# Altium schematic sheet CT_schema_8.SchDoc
size 277 x 170 mm
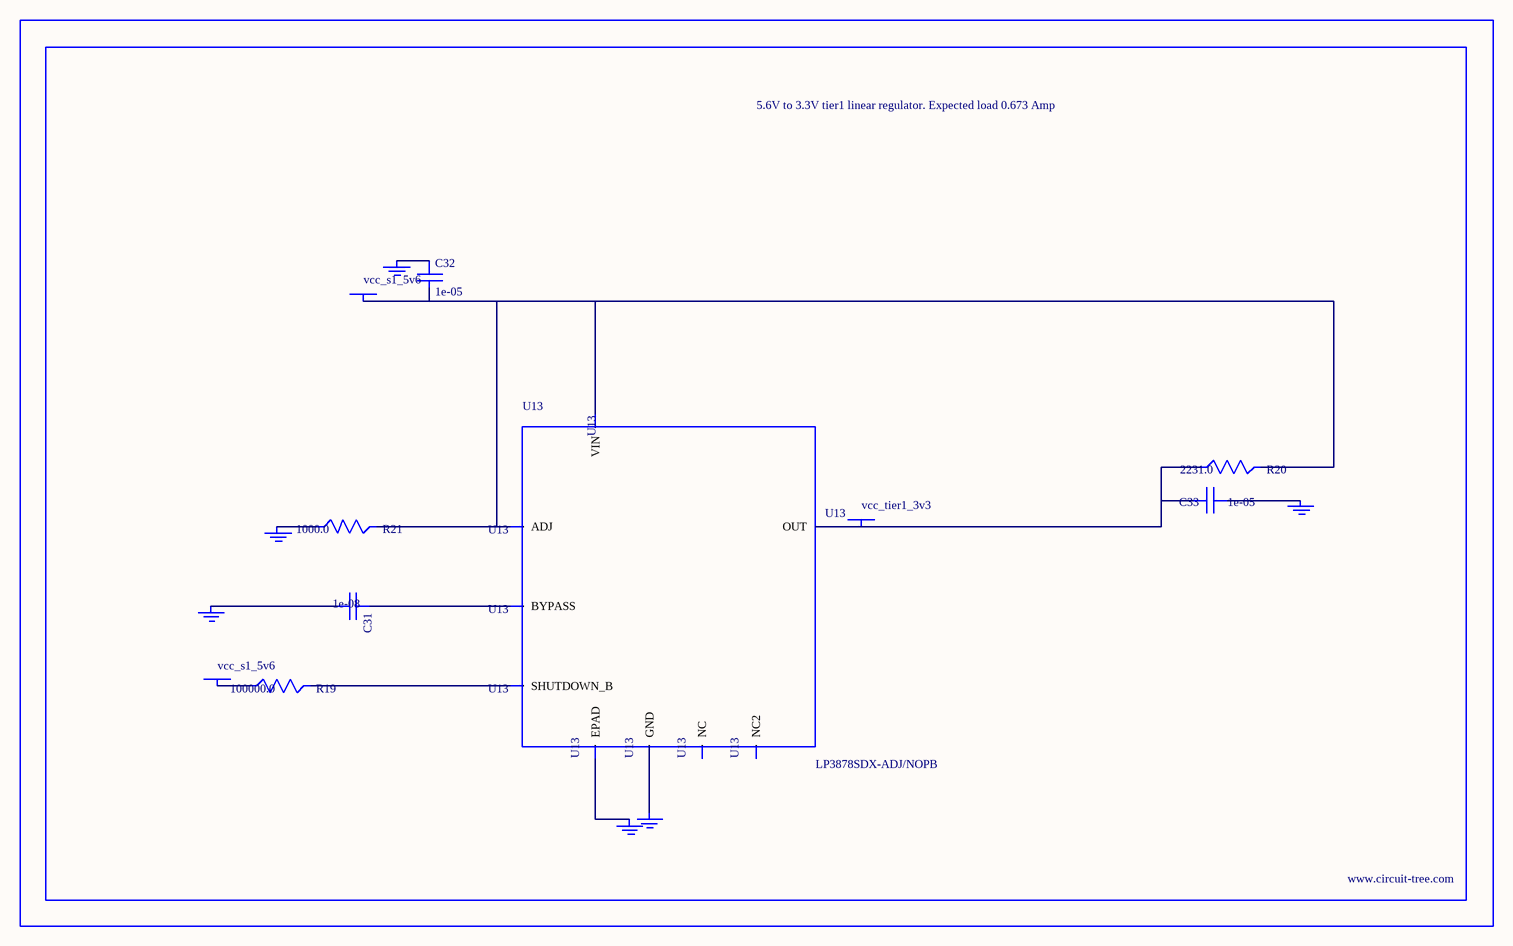
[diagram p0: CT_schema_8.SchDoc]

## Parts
BORDER7  (no value)
C31  1e-08  [C0402]
C32  1e-05  [C1206]
C33  1e-05  [C1210]
GND_INSTANCE_7_0  (no value)
GND_INSTANCE_7_1  (no value)
GND_INSTANCE_7_2  (no value)
GND_INSTANCE_7_3  (no value)
GND_INSTANCE_7_4  (no value)
GND_INSTANCE_7_5  (no value)
POWER_INSTANCE_7_0  vcc_s1_5v6
POWER_INSTANCE_7_1  vcc_s1_5v6
POWER_INSTANCE_7_2  vcc_tier1_3v3
R19  100000.0  [R0603]
R20  2231.0  [R0603]
R21  1000.0  [R0603]
U13  LP3878SDX-ADJ/NOPB  [WSON-8]

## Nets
NetC31_1: C31.1 U13.1(BYPASS)
NetC31_2: C31.2 GND_INSTANCE_7_0.0(GND)
NetC32_1: C32.1 GND_INSTANCE_7_1.0(GND)
NetC32_2: C32.2 POWER_INSTANCE_7_0.0(PWR) R20.2 R21.2 U13.4(VIN) U13.6(ADJ)
NetC33_1: C33.1 GND_INSTANCE_7_2.0(GND)
NetC33_2: C33.2 POWER_INSTANCE_7_2.0(PWR) R20.1 U13.5(OUT)
NetGND_INSTANCE_7_3_0: GND_INSTANCE_7_3.0(GND) R21.1
NetGND_INSTANCE_7_4_0: GND_INSTANCE_7_4.0(GND) U13.PAD(EPAD)
NetGND_INSTANCE_7_5_0: GND_INSTANCE_7_5.0(GND) U13.3(GND)
NetPOWER_INSTANCE_7_1_0: POWER_INSTANCE_7_1.0(PWR) R19.1
NetR19_2: R19.2 U13.8(SHUTDOWN_B)

Not connected (* = marked no-connect by the designer): U13 2(NC) 7(NC2)

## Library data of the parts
BORDER7 = BORDER_PAGE7
C31 = C0402C103K3RAC
C32 = C1206C106K3RACTU
C33 = GRM32DR61E106MA12L
GND_INSTANCE_7_0-GND_INSTANCE_7_5 = GND
POWER_INSTANCE_7_0-POWER_INSTANCE_7_2 = PWR
R19 = RC0603JR-07100KL
R20 = R20
R21 = RC0603JR-071KL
